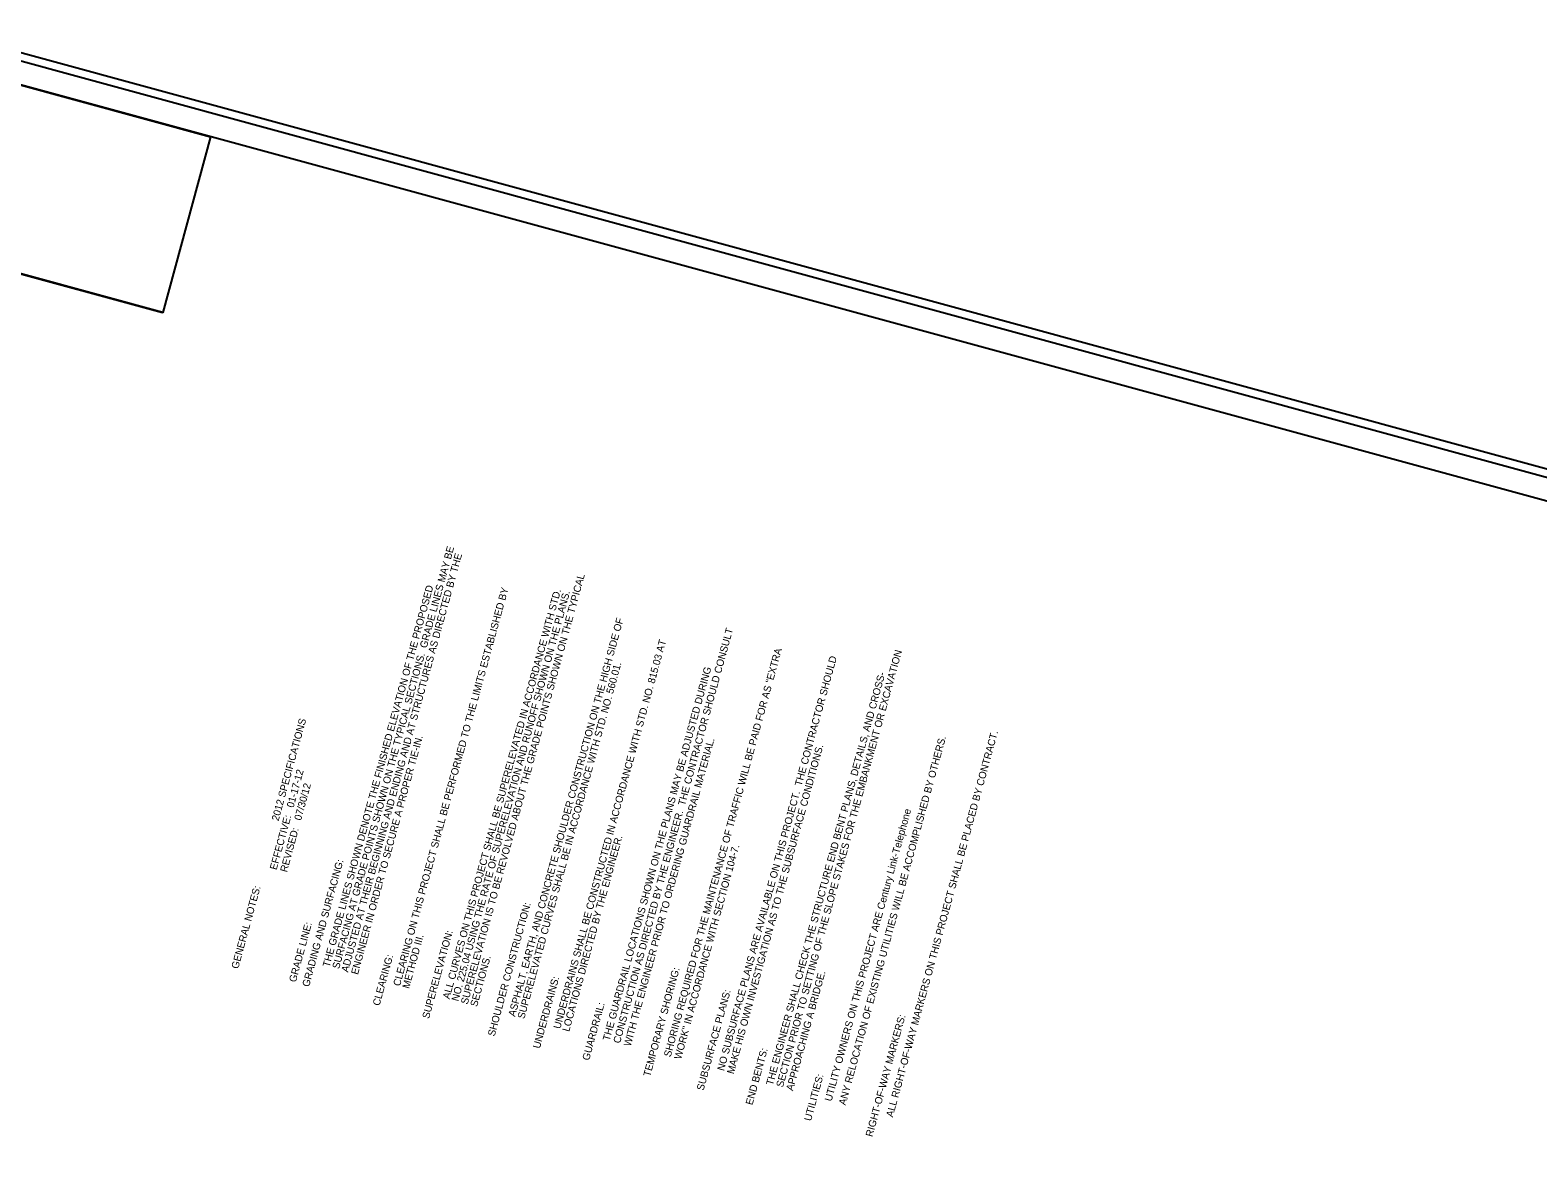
# Model space of a CAD drawing. Extents: x 2076126 to 2079903, y 925480 to 928006.
# Drawn here: x 2076620 to 2077447, y 927387 to 928006 of the extents above; entities that cross this region are included whole.
import ezdxf

# ---------------------------------------------------------------- set-up
doc = ezdxf.new("R2010")
doc.units = 0
for name, color, linetype in [('Default', 7, 'Continuous'), ('Sheet Plan CELL', 7, 'Continuous'), ('Sheet Plot Border Inside CELL', 7, 'Continuous'), ('Sheet Plot Border Outside CELL', 7, 'Continuous')]:
    doc.layers.add(name, color=color, linetype=linetype)

msp = doc.modelspace()

# ---------------------------------------------------------------- linework, layer by layer
at = {"layer": 'Sheet Plan CELL'}
msp.add_line((2076583.98, 927880.48), (2076692.47, 927850.89), dxfattribs=at)
for points in [[(2076586.13, 927983.55), (2076191.41, 926536.41), (2077204.41, 926260.12), (2077599.12, 927707.25)], [(2076583.98, 927880.48), (2076610.29, 927976.96), (2076718.83, 927947.35), (2076692.52, 927850.88)]]:
    msp.add_lwpolyline(points, close=True, dxfattribs=at)
at = {"layer": 'Sheet Plot Border Inside CELL'}
msp.add_lwpolyline([(2077166.43, 926111.37), (2077604.82, 927718.65), (2076587, 927996.27), (2076148.61, 926388.98)], close=True, dxfattribs=at)
at = {"layer": 'Sheet Plot Border Outside CELL'}
msp.add_lwpolyline([(2077182.3, 926093.56), (2077625.3, 927717.73), (2076568.89, 928005.87), (2076125.89, 926381.7)], close=True, dxfattribs=at)

# ---------------------------------------------------------------- texts
at = {"layer": 'Default'}
for s, p in [('         SURFACING AT GRADE POINTS SHOWN ON THE TYPICAL SECTIONS.  GRADE LINES MAY BE ', (2076785.83, 927477.44)), ('         ADJUSTED AT THEIR BEGINNING AND ENDING AND AT STRUCTURES AS DIRECTED BY THE ', (2076790.75, 927475.61)), ('         SUPERELEVATION IS TO BE REVOLVED ABOUT THE GRADE POINTS SHOWN ON THE TYPICAL ', (2076856.37, 927458.02)), ('         THE GRADE LINES SHOWN DENOTE THE FINISHED ELEVATION OF THE PROPOSED ', (2076780.56, 927478.39)), ('         CLEARING ON THIS PROJECT SHALL BE PERFORMED TO THE LIMITS ESTABLISHED BY ', (2076819.24, 927468)), ('         ALL CURVES ON THIS PROJECT SHALL BE SUPERELEVATED IN ACCORDANCE WITH STD. ', (2076846.42, 927460.92)), ('         NO. 225.04 USING THE RATE OF SUPERELEVATION AND RUNOFF SHOWN ON THE PLANS.', (2076851.28, 927459.68)), ('         ASPHALT, EARTH, AND CONCRETE SHOULDER CONSTRUCTION ON THE HIGH SIDE OF', (2076882.4, 927451.28)), ('         CONSTRUCTION AS DIRECTED BY THE ENGINEER.  THE CONTRACTOR SHOULD CONSULT', (2076940.02, 927436.57)), ('         UNDERDRAINS SHALL BE CONSTRUCTED IN ACCORDANCE WITH STD. NO. 815.03 AT ', (2076907.2, 927444.51)), ('         SHORING REQUIRED FOR THE MAINTENANCE OF TRAFFIC WILL BE PAID FOR AS "EXTRA ', (2076967.79, 927429.12)), ('         SECTION PRIOR TO SETTING OF THE SLOPE STAKES FOR THE EMBANKMENT OR EXCAVATION ', (2077029.46, 927412.5)), ('         SUPERELEVATED CURVES SHALL BE IN ACCORDANCE WITH STD. NO. 560.01.', (2076887.48, 927450.05)), ('         THE GUARDRAIL LOCATIONS SHOWN ON THE PLANS MAY BE ADJUSTED DURING ', (2076934.27, 927437.97)), ('         NO SUBSURFACE PLANS ARE AVAILABLE ON THIS PROJECT.  THE CONTRACTOR SHOULD ', (2076997.06, 927421.49)), ('         THE ENGINEER SHALL CHECK THE STRUCTURE END BENT PLANS, DETAILS, AND CROSS-', (2077023.92, 927413.52)), ('GENERAL NOTES:                         2012 SPECIFICATIONS', (2076733.96, 927490.38)), ('         ENGINEER IN ORDER TO SECURE A PROPER TIE-IN.  ', (2076796.15, 927474.3)), ('         WITH THE ENGINEER PRIOR TO ORDERING GUARDRAIL MATERIAL.', (2076945.8, 927434.83)), ('         ANY RELOCATION OF EXISTING UTILITIES WILL BE ACCOMPLISHED BY OTHERS.  ', (2077063.8, 927402.64)), ('         ALL RIGHT-OF-WAY MARKERS ON THIS PROJECT SHALL BE PLACED BY CONTRACT.  ', (2077089.76, 927396.06)), ('         MAKE HIS OWN INVESTIGATION AS TO THE SUBSURFACE CONDITIONS.  ', (2077002.43, 927419.74)), ('                                       EFFECTIVE:   01-17-12', (2076739.78, 927488.79)), ('                                       REVISED:   07/30/12', (2076745.47, 927487.53)), ('         UTILITY OWNERS ON THIS PROJECT ARE Century Link-Telephone', (2077056.08, 927404.75)), ('         LOCATIONS DIRECTED BY THE ENGINEER.  ', (2076912.09, 927443.01)), ('         WORK" IN ACCORDANCE WITH SECTION 104-7.  ', (2076973.49, 927427.73)), ('GRADING AND SURFACING:  ', (2076772.84, 927480.49)), ('SHOULDER CONSTRUCTION:  ', (2076874.68, 927453.38)), ('GRADE LINE:  ', (2076765.6, 927483.04)), ('         METHOD III.', (2076824.24, 927466.64)), ('SUPERELEVATION:  ', (2076838.7, 927463.02)), ('CLEARING:  ', (2076811.52, 927470.11)), ('         SECTIONS.  ', (2076861.56, 927456.69)), ('TEMPORARY SHORING:  ', (2076960.07, 927431.22)), ('UNDERDRAINS:  ', (2076899.49, 927446.62)), ('         APPROACHING A BRIDGE.  ', (2077034.92, 927410.52)), ('SUBSURFACE PLANS:  ', (2076989.35, 927423.6)), ('GUARDRAIL:  ', (2076926.55, 927440.08)), ('RIGHT-OF-WAY MARKERS:  ', (2077082.05, 927398.17)), ('END BENTS:  ', (2077016.2, 927415.62)), ('UTILITIES:  ', (2077048.36, 927406.85))]:
    msp.add_text(s, height=4, rotation=74.7434, dxfattribs=at).set_placement(p)

doc.saveas('drawing.dxf')
